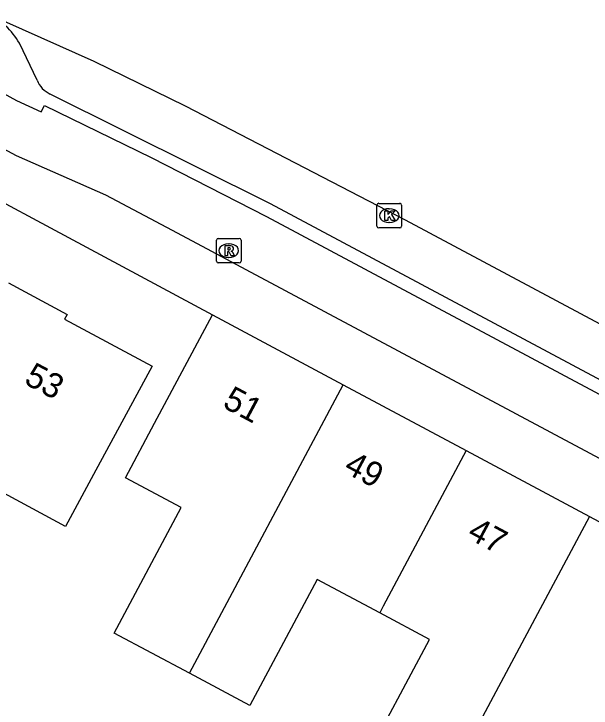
# Model space of a CAD drawing. Extents: x 159265 to 160143, y 383413 to 384319.
# Drawn here: x 159811.65 to 159835.14, y 383951.41 to 383979.65 of the extents above; entities that cross this region are included whole.
import ezdxf

# ---------------------------------------------------------------- set-up
doc = ezdxf.new("R2010")
doc.units = 0
for name, color, linetype in [('IMGEO_Fietspad_gesloten', 7, 'Continuous'), ('IMGEO_Kolk', 7, 'Continuous'), ('IMGEO_Pand', 7, 'Continuous'), ('IMGEO_Pand_nummerreeks', 7, 'Continuous'), ('IMGEO_Parkeervlak_open', 7, 'Continuous'), ('IMGEO_Rijbaan_lokaal_gesloten', 7, 'Continuous'), ('IMGEO_Rioolput', 7, 'Continuous'), ('IMGEO_Voetpad_open', 7, 'Continuous')]:
    doc.layers.add(name, color=color, linetype=linetype)

msp = doc.modelspace()

# ---------------------------------------------------------------- linework, layer by layer
at = {"layer": 'IMGEO_Fietspad_gesloten'}
for points in [[(159878.488, 383938.609), (159818.103, 383970.845), (159815.384, 383972.277), (159811.759, 383973.873), (159806.209, 383976.854), (159802.382, 383978.898)], [(159807.769, 383978.315), (159811.755, 383976.132), (159812.762, 383975.674), (159812.887, 383975.929), (159817.239, 383973.81), (159821.924, 383971.407), (159879.571, 383940.642)]]:
    msp.add_lwpolyline(points, dxfattribs=at)
at = {"layer": 'IMGEO_Kolk'}
for p, q in [((159826.424, 383971.019), (159826.424, 383971.871)), ((159826.499, 383971.945), (159827.351, 383971.945)), ((159827.425, 383971.871), (159827.425, 383971.019)), ((159826.912, 383971.725), (159826.937, 383971.725)), ((159826.935, 383971.165), (159826.91, 383971.165)), ((159827.351, 383970.945), (159826.499, 383970.945))]:
    msp.add_line(p, q, dxfattribs=at)
for points in [[(159826.424, 383971.019), (159826.424, 383971.871)], [(159826.499, 383971.945), (159827.351, 383971.945)], [(159827.425, 383971.871), (159827.425, 383971.019)], [(159826.745, 383971.645), (159826.868, 383971.645), (159826.868, 383971.494), (159826.998, 383971.645), (159827.162, 383971.645), (159827.016, 383971.494), (159827.169, 383971.245), (159827.017, 383971.245), (159826.932, 383971.409), (159826.868, 383971.342), (159826.868, 383971.245), (159826.745, 383971.245), (159826.745, 383971.645)], [(159827.351, 383970.945), (159826.499, 383970.945)]]:
    msp.add_lwpolyline(points, dxfattribs=at)
for centre, start, end in [((159826.501, 383971.869), 91.552, 178.448), ((159826.501, 383971.869), 91.552, 178.448), ((159827.349, 383971.869), 1.552, 88.448), ((159827.349, 383971.869), 1.552, 88.448), ((159826.501, 383971.021), 181.552, 268.448), ((159826.501, 383971.021), 181.552, 268.448), ((159827.349, 383971.021), 271.552, 358.448), ((159827.349, 383971.021), 271.552, 358.448)]:
    msp.add_arc(centre, 0.0765, start, end, dxfattribs=at)
for centre, major_axis, ratio, start_param, end_param in [((159826.911, 383971.445), (-0.387, 0.002), 0.722429, 4.712389, 7.853982), ((159826.936, 383971.445), (-0.39, 0.002), 0.717154, 1.570796, 4.712389)]:
    msp.add_ellipse(centre, major_axis=major_axis, ratio=ratio, start_param=start_param, end_param=end_param, dxfattribs=at)
at = {"layer": 'IMGEO_Pand'}
for points in [[(159811.423, 383968.704), (159813.812, 383967.428), (159813.708, 383967.233), (159817.271, 383965.319), (159814.887, 383960.909), (159813.743, 383958.792), (159809.074, 383961.315), (159808.051, 383959.422), (159809.219, 383958.79), (159807.462, 383955.543), (159805.02, 383956.863)], [(159818.788, 383952.824), (159815.733, 383954.456), (159818.459, 383959.564), (159816.187, 383960.776), (159817.374, 383962.999), (159819.73, 383967.413)], [(159819.73, 383967.413), (159825.054, 383964.564)], [(159818.788, 383952.824), (159818.898, 383953.031), (159825.054, 383964.564)], [(159825.054, 383964.564), (159830.059, 383961.885)], [(159830.059, 383961.885), (159826.68, 383955.554), (159826.534, 383955.28)], [(159830.059, 383961.885), (159835.066, 383959.206)], [(159835.066, 383959.206), (159828.819, 383947.504), (159828.764, 383947.401)], [(159835.066, 383959.206), (159840.07, 383956.528)], [(159826.534, 383955.28), (159823.987, 383956.64), (159821.249, 383951.512), (159818.788, 383952.824)], [(159828.764, 383947.401), (159825.787, 383948.991), (159828.566, 383954.196), (159826.534, 383955.28)]]:
    msp.add_lwpolyline(points, dxfattribs=at)
at = {"layer": 'IMGEO_Parkeervlak_open'}
for points in [[(159812.591, 383976.96), (159811.872, 383978.463)], [(159885.523, 383938.052), (159822.09, 383971.919), (159813.13, 383976.392)]]:
    msp.add_lwpolyline(points, dxfattribs=at)
for centre, radius, start, end in [((159809.372, 383977.039), 2.877, 29.666, 65.3052), ((159813.557, 383977.337), 1.037, 201.3196, 245.6792)]:
    msp.add_arc(centre, radius, start, end, dxfattribs=at)
at = {"layer": 'IMGEO_Rijbaan_lokaal_gesloten'}
msp.add_lwpolyline([(159810.574, 383979.653), (159814.9, 383977.723), (159818.616, 383975.911), (159827.568, 383971.273), (159889.226, 383938.344)], dxfattribs=at)
at = {"layer": 'IMGEO_Rioolput'}
for p, q in [((159819.966, 383970.52), (159820.818, 383970.52)), ((159819.891, 383969.594), (159819.891, 383970.446)), ((159820.379, 383970.3), (159820.404, 383970.3)), ((159820.892, 383970.446), (159820.892, 383969.594)), ((159820.402, 383969.74), (159820.377, 383969.74)), ((159820.818, 383969.52), (159819.966, 383969.52))]:
    msp.add_line(p, q, dxfattribs=at)
for points in [[(159819.966, 383970.52), (159820.818, 383970.52)], [(159819.891, 383969.594), (159819.891, 383970.446)], [(159820.48, 383970.218), (159820.228, 383970.22), (159820.228, 383969.82)], [(159820.892, 383970.446), (159820.892, 383969.594)], [(159820.228, 383969.82), (159820.352, 383969.82), (159820.352, 383969.982), (159820.363, 383969.982)], [(159820.406, 383970.139), (159820.352, 383970.139), (159820.352, 383970.058)], [(159820.352, 383970.058), (159820.404, 383970.058)], [(159820.41, 383969.953), (159820.481, 383969.82), (159820.621, 383969.82), (159820.556, 383969.946)], [(159820.818, 383969.52), (159819.966, 383969.52)]]:
    msp.add_lwpolyline(points, dxfattribs=at)
for centre, radius, start, end in [((159819.968, 383970.444), 0.0765, 91.552, 178.448), ((159819.968, 383970.444), 0.0765, 91.552, 178.448), ((159820.816, 383970.444), 0.0765, 1.552, 88.448), ((159820.816, 383970.444), 0.0765, 1.552, 88.448), ((159820.479, 383970.108), 0.109, 350.3612, 89.416), ((159820.362, 383969.929), 0.0533, 26.0293, 88.6989), ((159820.388, 383970.247), 0.19, 274.7715, 282.9687), ((159820.412, 383970.043), 0.0964, 77.0061, 93.1865), ((159820.426, 383970.1), 0.0378, 276.6634, 79.6772), ((159820.477, 383970.108), 0.112, 277.5842, 350.9817), ((159820.461, 383969.893), 0.108, 29.5134, 73.7905), ((159819.968, 383969.596), 0.0765, 181.552, 268.448), ((159819.968, 383969.596), 0.0765, 181.552, 268.448), ((159820.816, 383969.596), 0.0765, 271.552, 358.448), ((159820.816, 383969.596), 0.0765, 271.552, 358.448)]:
    msp.add_arc(centre, radius, start, end, dxfattribs=at)
for centre, major_axis, ratio, start_param, end_param in [((159820.378, 383970.02), (-0.387, 0.002), 0.722429, 4.712389, 7.853982), ((159820.403, 383970.02), (-0.39, 0.002), 0.717154, 1.570796, 4.712389)]:
    msp.add_ellipse(centre, major_axis=major_axis, ratio=ratio, start_param=start_param, end_param=end_param, dxfattribs=at)
at = {"layer": 'IMGEO_Voetpad_open'}
msp.add_lwpolyline([(159804.154, 383975.767), (159819.73, 383967.413)], dxfattribs=at)

# ---------------------------------------------------------------- texts
at = {"layer": 'IMGEO_Pand_nummerreeks'}
for s, rotation, p in [('53', 332.1256, (159812.015, 383964.629)), ('51', 331.8334, (159820.094, 383963.673)), ('49', 331.8334, (159825.021, 383961.035)), ('47', 331.8334, (159830.049, 383958.343))]:
    msp.add_text(s, height=1, rotation=rotation, dxfattribs=at).set_placement(p)

doc.saveas('drawing.dxf')
